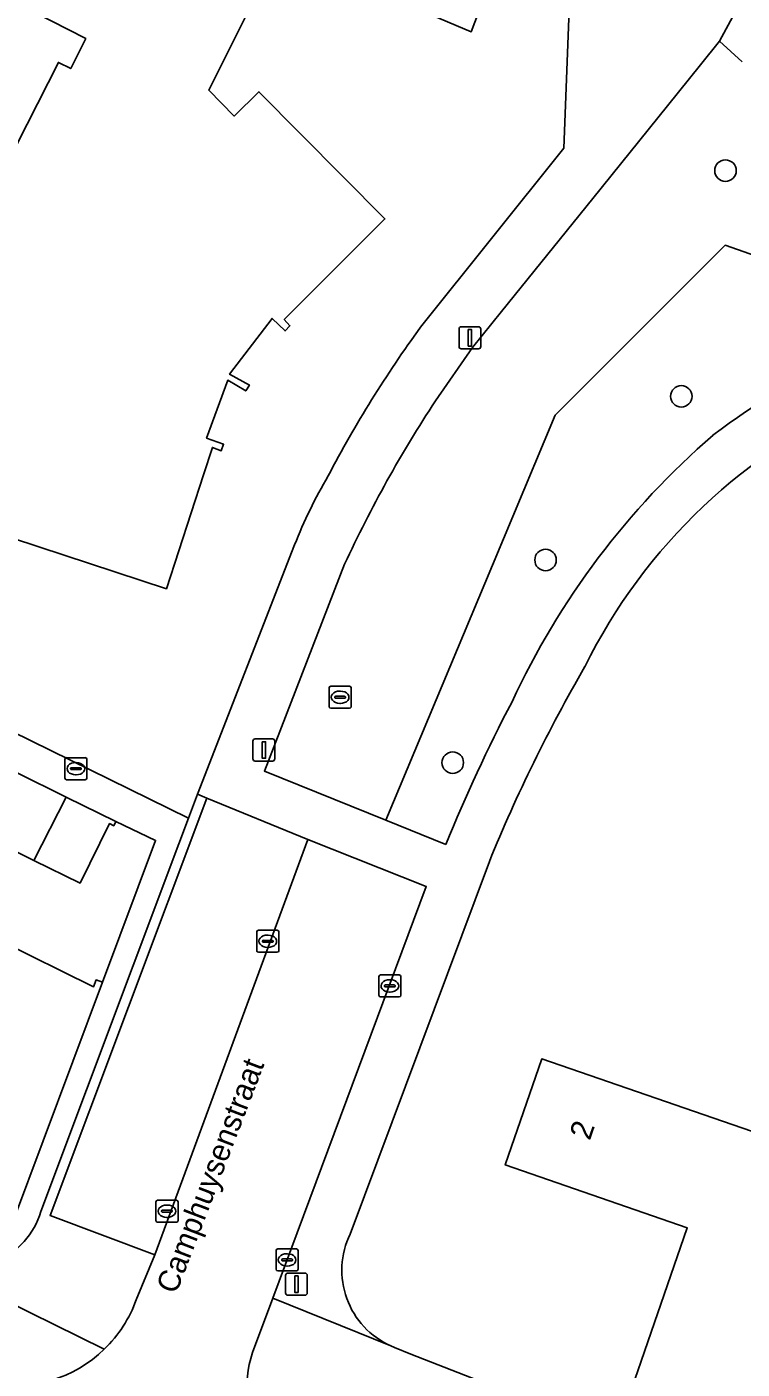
# Model space of a CAD drawing. Extents: x 160349 to 161355, y 381727 to 382854.
# Drawn here: x 160579.4 to 160611.9, y 381959.4 to 382020.3 of the extents above; entities that cross this region are included whole.
import ezdxf

# ---------------------------------------------------------------- set-up
doc = ezdxf.new("R2010")
doc.units = 0
for name, color, linetype in [('IMGEO_Boom', 7, 'Continuous'), ('IMGEO_Erf', 7, 'Continuous'), ('IMGEO_Groenvoorziening', 7, 'Continuous'), ('IMGEO_Kolk', 7, 'Continuous'), ('IMGEO_Lichtmast', 7, 'Continuous'), ('IMGEO_Muur', 7, 'Continuous'), ('IMGEO_Openbare_ruimte_label', 7, 'Continuous'), ('IMGEO_Pand', 7, 'Continuous'), ('IMGEO_Pand_nummerreeks', 7, 'Continuous'), ('IMGEO_Parkeervlak_open', 7, 'Continuous'), ('IMGEO_Rijbaan_lokaal_open', 7, 'Continuous'), ('IMGEO_Rioolput', 7, 'Continuous'), ('IMGEO_Voetpad_open', 7, 'Continuous')]:
    doc.layers.add(name, color=color, linetype=linetype)

msp = doc.modelspace()

# ---------------------------------------------------------------- linework, layer by layer
at = {"layer": 'IMGEO_Boom'}
for centre in [(160611.095, 382013.81), (160609.09, 382003.562), (160602.927, 381996.132), (160598.714, 381986.931)]:
    msp.add_circle(centre, 0.489, dxfattribs=at)
at = {"layer": 'IMGEO_Erf'}
for points in [[(160582.049, 382019.806), (160567.258, 382027.358), (160569.969, 382032.694), (160568.184, 382033.456), (160568.223, 382033.56), (160567.62, 382033.798), (160563.756, 382026.216), (160561.616, 382027.336), (160561.005, 382026.029), (160561.7, 382025.66), (160561.631, 382025.459), (160561.904, 382025.308), (160561.543, 382019.82), (160560.417, 381999.666), (160555.404, 381999.955), (160555.394, 381999.801), (160586.709, 381984.411), (160587.131, 381985.496), (160591.533, 381996.816)], [(160597.255, 382006.702), (160603.75, 382014.83), (160604.192, 382026.239)], [(160601.348, 382024.877), (160599.551, 382020.118), (160596.039, 382021.61)], [(160590.819, 382023.827), (160587.632, 382017.457), (160588.796, 382016.283), (160589.91, 382017.389), (160595.637, 382011.618), (160591.061, 382007.043), (160591.321, 382006.766), (160591.1, 382006.532), (160590.512, 382007.1), (160588.582, 382004.564), (160589.479, 382004.075), (160589.314, 382003.805), (160588.496, 382004.296), (160587.535, 382001.665), (160588.306, 382001.384), (160588.2, 382001.093), (160587.802, 382001.24), (160587.398, 382000), (160585.711, 381994.824), (160577.553, 381997.498)], [(160577.958, 382013.117), (160580.81, 382018.725), (160581.372, 382018.44), (160582.049, 382019.806)], [(160578.111, 381978.874), (160582.404, 381976.755), (160582.522, 381977.069), (160582.816, 381976.971), (160585.222, 381983.402), (160583.415, 381984.257), (160583.319, 381984.063), (160583.13, 381984.167), (160581.792, 381981.46), (160579.691, 381982.494), (160577.59, 381983.528)], [(160600.376, 381982.448), (160594.057, 381965.531)], [(160635.384, 381980.363), (160635.293, 381979.403), (160629.147, 381969.866), (160626.967, 381970.618), (160624.197, 381962.588), (160616.551, 381965.226), (160613.54, 381956.498), (160613.822, 381956.401), (160613.572, 381955.675), (160606.683, 381958.052), (160609.361, 381965.817), (160601.095, 381968.668), (160602.754, 381973.481), (160618.335, 381968.106), (160620.023, 381972.998), (160616.368, 381974.259), (160616.133, 381980.304), (160614.523, 381980.875)], [(160595.906, 381960.451), (160596.062, 381960.385), (160596.803, 381960.076), (160647.902, 381940.147)]]:
    msp.add_lwpolyline(points, dxfattribs=at)
for centre, radius, start, end in [((160640.632, 381975.066), 53.688, 143.89551, 152.38709), ((160627.701, 381979.922), 25.647, 113.12706, 153.69167), ((160612.091, 381988.744), 22.086, 149.51159, 158.56387), ((160667.438, 381955.049), 72.444, 149.98309, 157.77679), ((160597.437, 381963.885), 3.76, 154.03613, 245.96449)]:
    msp.add_arc(centre, radius, start, end, dxfattribs=at)
at = {"layer": 'IMGEO_Groenvoorziening'}
for points in [[(160611.853, 382018.745), (160610.821, 382019.688), (160609.956, 382018.614), (160608.46, 382016.757), (160605.07, 382012.549), (160600.93, 382007.409), (160599.614, 382005.776), (160597.93, 382003.354)], [(160593.801, 381995.937), (160590.164, 381986.55), (160595.677, 381984.32), (160600.512, 381995.895), (160603.366, 382002.7), (160611.086, 382010.42), (160614.745, 382009.139), (160618.989, 382008.371), (160622.943, 382011.327)], [(160623.793, 382007.511), (160622.943, 382011.327), (160618.989, 382008.371), (160614.745, 382009.139), (160611.086, 382010.42), (160603.366, 382002.7), (160600.512, 381995.895), (160595.677, 381984.32), (160598.403, 381983.217)]]:
    msp.add_lwpolyline(points, dxfattribs=at)
for centre, radius, start, end in [((160628.359, 381978.679), 29.191, 98.99987, 127.64836), ((160645.815, 381971.839), 57.325, 146.6494, 155.14174), ((160633.977, 381974.621), 35.889, 130.7934, 155.17039), ((160665.558, 381956.015), 72.455, 152.30312, 157.94924)]:
    msp.add_arc(centre, radius, start, end, dxfattribs=at)
at = {"layer": 'IMGEO_Kolk'}
for p, q in [((160581.105, 381986.231), (160581.105, 381987.083)), ((160581.18, 381987.157), (160582.032, 381987.157)), ((160581.593, 381986.937), (160581.618, 381986.937)), ((160582.106, 381987.083), (160582.106, 381986.231)), ((160581.364, 381986.651), (160581.364, 381986.663)), ((160581.802, 381986.614), (160581.404, 381986.614)), ((160581.407, 381986.7), (160581.805, 381986.7)), ((160581.616, 381986.377), (160581.591, 381986.377)), ((160581.848, 381986.663), (160581.848, 381986.651)), ((160582.032, 381986.157), (160581.18, 381986.157)), ((160589.816, 381978.395), (160589.816, 381979.247)), ((160589.891, 381979.321), (160590.743, 381979.321)), ((160590.304, 381979.101), (160590.329, 381979.101)), ((160590.817, 381979.247), (160590.817, 381978.395)), ((160590.075, 381978.815), (160590.075, 381978.827)), ((160590.513, 381978.778), (160590.115, 381978.778)), ((160590.118, 381978.864), (160590.516, 381978.864)), ((160590.327, 381978.541), (160590.302, 381978.541)), ((160590.559, 381978.827), (160590.559, 381978.815)), ((160590.743, 381978.321), (160589.891, 381978.321)), ((160595.358, 381976.368), (160595.358, 381977.22)), ((160595.433, 381977.294), (160596.285, 381977.294)), ((160596.359, 381977.22), (160596.359, 381976.368)), ((160595.617, 381976.788), (160595.617, 381976.8)), ((160596.055, 381976.751), (160595.657, 381976.751)), ((160595.66, 381976.837), (160596.058, 381976.837)), ((160595.869, 381976.514), (160595.844, 381976.514)), ((160595.846, 381977.074), (160595.871, 381977.074)), ((160596.101, 381976.8), (160596.101, 381976.788)), ((160596.285, 381976.294), (160595.433, 381976.294)), ((160585.239, 381966.14), (160585.239, 381966.992)), ((160585.314, 381967.066), (160586.166, 381967.066)), ((160585.727, 381966.846), (160585.752, 381966.846)), ((160586.24, 381966.992), (160586.24, 381966.14)), ((160585.498, 381966.56), (160585.498, 381966.572)), ((160585.936, 381966.523), (160585.538, 381966.523)), ((160585.541, 381966.609), (160585.939, 381966.609)), ((160585.75, 381966.286), (160585.725, 381966.286)), ((160585.982, 381966.572), (160585.982, 381966.56)), ((160586.166, 381966.066), (160585.314, 381966.066)), ((160590.692, 381963.928), (160590.692, 381964.78)), ((160590.767, 381964.854), (160591.619, 381964.854)), ((160590.951, 381964.348), (160590.951, 381964.36)), ((160590.994, 381964.397), (160591.392, 381964.397)), ((160591.18, 381964.634), (160591.205, 381964.634)), ((160591.435, 381964.36), (160591.435, 381964.348)), ((160591.693, 381964.78), (160591.693, 381963.928)), ((160591.619, 381963.854), (160590.767, 381963.854)), ((160591.389, 381964.311), (160590.991, 381964.311)), ((160591.203, 381964.074), (160591.178, 381964.074))]:
    msp.add_line(p, q, dxfattribs=at)
for points in [[(160581.105, 381986.231), (160581.105, 381987.083)], [(160581.18, 381987.157), (160582.032, 381987.157)], [(160582.106, 381987.083), (160582.106, 381986.231)], [(160582.032, 381986.157), (160581.18, 381986.157)], [(160589.816, 381978.395), (160589.816, 381979.247)], [(160589.891, 381979.321), (160590.743, 381979.321)], [(160590.817, 381979.247), (160590.817, 381978.395)], [(160590.743, 381978.321), (160589.891, 381978.321)], [(160595.358, 381976.368), (160595.358, 381977.22)], [(160595.433, 381977.294), (160596.285, 381977.294)], [(160596.359, 381977.22), (160596.359, 381976.368)], [(160596.285, 381976.294), (160595.433, 381976.294)], [(160585.239, 381966.14), (160585.239, 381966.992)], [(160585.314, 381967.066), (160586.166, 381967.066)], [(160586.24, 381966.992), (160586.24, 381966.14)], [(160586.166, 381966.066), (160585.314, 381966.066)], [(160590.692, 381963.928), (160590.692, 381964.78)], [(160590.767, 381964.854), (160591.619, 381964.854)], [(160591.693, 381964.78), (160591.693, 381963.928)], [(160591.619, 381963.854), (160590.767, 381963.854)]]:
    msp.add_lwpolyline(points, dxfattribs=at)
for centre, radius, start, end in [((160581.182, 381987.081), 0.0765, 91.55205, 178.44795), ((160581.182, 381987.081), 0.0765, 91.55205, 178.44795), ((160582.03, 381987.081), 0.0765, 1.55205, 88.44795), ((160582.03, 381987.081), 0.0765, 1.55205, 88.44795), ((160581.404, 381986.66), 0.0403, 85.87752, 175.75265), ((160581.401, 381986.65), 0.0366, 178.93798, 274.71019), ((160581.805, 381986.657), 0.043, 264.86636, 352.45326), ((160581.809, 381986.662), 0.0386, 1.73085, 96.63898), ((160581.182, 381986.233), 0.0765, 181.55205, 268.44795), ((160581.182, 381986.233), 0.0765, 181.55205, 268.44795), ((160582.03, 381986.233), 0.0765, 271.55205, 358.44795), ((160582.03, 381986.233), 0.0765, 271.55205, 358.44795), ((160589.893, 381979.245), 0.0765, 91.55205, 178.44795), ((160589.893, 381979.245), 0.0765, 91.55205, 178.44795), ((160590.741, 381979.245), 0.0765, 1.55205, 88.44795), ((160590.741, 381979.245), 0.0765, 1.55205, 88.44795), ((160589.893, 381978.397), 0.0765, 181.55205, 268.44795), ((160589.893, 381978.397), 0.0765, 181.55205, 268.44795), ((160590.115, 381978.824), 0.0403, 85.87752, 175.75265), ((160590.112, 381978.814), 0.0366, 178.93798, 274.71019), ((160590.516, 381978.821), 0.043, 264.86636, 352.45326), ((160590.52, 381978.826), 0.0386, 1.73085, 96.63898), ((160590.741, 381978.397), 0.0765, 271.55205, 358.44795), ((160590.741, 381978.397), 0.0765, 271.55205, 358.44795), ((160595.435, 381977.218), 0.0765, 91.55205, 178.44795), ((160595.435, 381977.218), 0.0765, 91.55205, 178.44795), ((160596.283, 381977.218), 0.0765, 1.55205, 88.44795), ((160596.283, 381977.218), 0.0765, 1.55205, 88.44795), ((160595.657, 381976.797), 0.0403, 85.87752, 175.75265), ((160595.654, 381976.787), 0.0366, 178.93798, 274.71019), ((160596.058, 381976.794), 0.043, 264.86636, 352.45326), ((160596.062, 381976.799), 0.0386, 1.73085, 96.63898), ((160595.435, 381976.37), 0.0765, 181.55205, 268.44795), ((160595.435, 381976.37), 0.0765, 181.55205, 268.44795), ((160596.283, 381976.37), 0.0765, 271.55205, 358.44795), ((160596.283, 381976.37), 0.0765, 271.55205, 358.44795), ((160585.316, 381966.99), 0.0765, 91.55205, 178.44795), ((160585.316, 381966.99), 0.0765, 91.55205, 178.44795), ((160586.164, 381966.99), 0.0765, 1.55205, 88.44795), ((160586.164, 381966.99), 0.0765, 1.55205, 88.44795), ((160585.538, 381966.569), 0.0403, 85.87752, 175.75265), ((160585.535, 381966.559), 0.0366, 178.93798, 274.71019), ((160585.939, 381966.566), 0.043, 264.86636, 352.45326), ((160585.943, 381966.571), 0.0386, 1.73085, 96.63898), ((160585.316, 381966.142), 0.0765, 181.55205, 268.44795), ((160585.316, 381966.142), 0.0765, 181.55205, 268.44795), ((160586.164, 381966.142), 0.0765, 271.55205, 358.44795), ((160586.164, 381966.142), 0.0765, 271.55205, 358.44795), ((160590.769, 381964.778), 0.0765, 91.55205, 178.44795), ((160590.769, 381964.778), 0.0765, 91.55205, 178.44795), ((160590.991, 381964.357), 0.0403, 85.87752, 175.75265), ((160590.988, 381964.347), 0.0366, 178.93798, 274.71019), ((160591.392, 381964.354), 0.043, 264.86636, 352.45326), ((160591.396, 381964.359), 0.0386, 1.73085, 96.63898), ((160591.617, 381964.778), 0.0765, 1.55205, 88.44795), ((160591.617, 381964.778), 0.0765, 1.55205, 88.44795), ((160590.769, 381963.93), 0.0765, 181.55205, 268.44795), ((160590.769, 381963.93), 0.0765, 181.55205, 268.44795), ((160591.617, 381963.93), 0.0765, 271.55205, 358.44795), ((160591.617, 381963.93), 0.0765, 271.55205, 358.44795)]:
    msp.add_arc(centre, radius, start, end, dxfattribs=at)
for centre, major_axis, ratio, start_param, end_param in [((160581.592, 381986.657), (-0.387, 0.002), 0.722429, 4.712389, 7.853982), ((160581.617, 381986.657), (-0.39, 0.002), 0.717154, 1.570796, 4.712389), ((160590.303, 381978.821), (-0.387, 0.002), 0.722429, 4.712389, 7.853982), ((160590.328, 381978.821), (-0.39, 0.002), 0.717154, 1.570796, 4.712389), ((160595.845, 381976.794), (-0.387, 0.002), 0.722429, 4.712389, 7.853982), ((160595.87, 381976.794), (-0.39, 0.002), 0.717154, 1.570796, 4.712389), ((160585.726, 381966.566), (-0.387, 0.002), 0.722429, 4.712389, 7.853982), ((160585.751, 381966.566), (-0.39, 0.002), 0.717154, 1.570796, 4.712389), ((160591.179, 381964.354), (-0.387, 0.002), 0.722429, 4.712389, 7.853982), ((160591.204, 381964.354), (-0.39, 0.002), 0.717154, 1.570796, 4.712389)]:
    msp.add_ellipse(centre, major_axis=major_axis, ratio=ratio, start_param=start_param, end_param=end_param, dxfattribs=at)
at = {"layer": 'IMGEO_Lichtmast'}
for p, q in [((160598.998, 382005.819), (160598.998, 382006.619)), ((160598.998, 382006.619), (160598.998, 382005.819)), ((160599.098, 382006.719), (160599.888, 382006.719)), ((160599.888, 382006.719), (160599.098, 382006.719)), ((160599.988, 382006.619), (160599.988, 382005.819)), ((160599.988, 382005.819), (160599.988, 382006.619)), ((160599.888, 382005.719), (160599.098, 382005.719)), ((160599.098, 382005.719), (160599.888, 382005.719)), ((160589.644, 381987.106), (160589.644, 381987.906)), ((160589.644, 381987.906), (160589.644, 381987.106)), ((160589.744, 381988.006), (160590.534, 381988.006)), ((160590.534, 381988.006), (160589.744, 381988.006)), ((160590.634, 381987.906), (160590.634, 381987.106)), ((160590.634, 381987.106), (160590.634, 381987.906)), ((160590.534, 381987.006), (160589.744, 381987.006)), ((160589.744, 381987.006), (160590.534, 381987.006)), ((160591.22, 381963.754), (160592.01, 381963.754)), ((160592.01, 381963.754), (160591.22, 381963.754)), ((160591.12, 381962.854), (160591.12, 381963.654)), ((160591.12, 381963.654), (160591.12, 381962.854)), ((160592.11, 381963.654), (160592.11, 381962.854)), ((160592.11, 381962.854), (160592.11, 381963.654)), ((160592.01, 381962.754), (160591.22, 381962.754)), ((160591.22, 381962.754), (160592.01, 381962.754))]:
    msp.add_line(p, q, dxfattribs=at)
for points in [[(160599.418, 382006.594), (160599.568, 382006.594), (160599.568, 382005.844), (160599.418, 382005.844), (160599.418, 382006.594)], [(160590.064, 381987.881), (160590.214, 381987.881), (160590.214, 381987.131), (160590.064, 381987.131), (160590.064, 381987.881)], [(160591.54, 381963.629), (160591.69, 381963.629), (160591.69, 381962.879), (160591.54, 381962.879), (160591.54, 381963.629)]]:
    msp.add_lwpolyline(points, dxfattribs=at)
for centre, start, end in [((160599.098, 382006.619), 90, 180), ((160599.098, 382006.619), 90, 180), ((160599.888, 382006.619), 0, 90), ((160599.888, 382006.619), 360, 90), ((160599.098, 382005.819), 180, 270), ((160599.098, 382005.819), 180, 270), ((160599.888, 382005.819), 270, 0), ((160599.888, 382005.819), 270, 0), ((160589.744, 381987.906), 90, 180), ((160589.744, 381987.906), 90, 180), ((160590.534, 381987.906), 0, 90), ((160590.534, 381987.906), 360, 90), ((160589.744, 381987.106), 180, 270), ((160589.744, 381987.106), 180, 270), ((160590.534, 381987.106), 270, 0), ((160590.534, 381987.106), 270, 0), ((160591.22, 381963.654), 90, 180), ((160591.22, 381963.654), 90, 180), ((160592.01, 381963.654), 0, 90), ((160592.01, 381963.654), 360, 90), ((160591.22, 381962.854), 180, 270), ((160591.22, 381962.854), 180, 270), ((160592.01, 381962.854), 270, 0), ((160592.01, 381962.854), 270, 0)]:
    msp.add_arc(centre, 0.1, start, end, dxfattribs=at)
at = {"layer": 'IMGEO_Muur'}
for points in [[(160583.415, 381984.257), (160585.222, 381983.402)], [(160585.222, 381983.402), (160582.816, 381976.971)]]:
    msp.add_lwpolyline(points, dxfattribs=at)
at = {"layer": 'IMGEO_Pand'}
for points in [[(160567.258, 382027.358), (160582.049, 382019.806), (160581.372, 382018.44), (160580.81, 382018.725), (160577.958, 382013.117)], [(160596.039, 382021.61), (160599.551, 382020.118), (160601.348, 382024.877)], [(160577.553, 381997.498), (160585.711, 381994.824), (160587.398, 382000), (160587.802, 382001.24), (160588.2, 382001.093), (160588.306, 382001.384), (160587.535, 382001.665), (160588.496, 382004.296), (160589.314, 382003.805), (160589.479, 382004.075), (160588.582, 382004.564), (160590.512, 382007.1), (160591.1, 382006.532), (160591.321, 382006.766), (160591.061, 382007.043), (160595.637, 382011.618), (160589.91, 382017.389), (160588.796, 382016.283), (160587.632, 382017.457), (160590.819, 382023.827)], [(160614.523, 381980.875), (160616.133, 381980.304), (160616.368, 381974.259), (160620.023, 381972.998), (160618.335, 381968.106), (160602.754, 381973.481), (160601.095, 381968.668), (160609.361, 381965.817), (160606.683, 381958.052), (160613.572, 381955.675), (160613.822, 381956.401), (160613.54, 381956.498), (160616.551, 381965.226), (160624.197, 381962.588), (160626.967, 381970.618), (160629.147, 381969.866), (160635.293, 381979.403), (160635.384, 381980.363), (160635.73, 381990.411), (160635.411, 381990.698), (160628.984, 381993.238), (160623.552, 381995.112), (160619.629, 381990.623), (160617.992, 381991.183)]]:
    msp.add_lwpolyline(points, dxfattribs=at)
for points in [[(160581.163, 381985.37), (160578.911, 381986.482), (160578.816, 381986.29), (160578.928, 381986.235), (160577.59, 381983.528), (160579.691, 381982.494)], [(160581.163, 381985.37), (160579.691, 381982.494), (160581.792, 381981.46), (160583.13, 381984.167), (160583.319, 381984.063), (160583.415, 381984.257)], [(160578.114, 381979.253), (160572.398, 381967.657), (160572.541, 381967.588), (160572.963, 381968.444), (160577.311, 381966.279), (160576.92, 381965.424), (160577.207, 381965.293), (160577.95, 381966.809), (160578.557, 381966.501), (160578.479, 381966.261), (160578.778, 381966.154), (160582.816, 381976.971), (160582.522, 381977.069), (160582.404, 381976.755), (160578.111, 381978.874), (160578.254, 381979.185)]]:
    msp.add_lwpolyline(points, close=True, dxfattribs=at)
at = {"layer": 'IMGEO_Parkeervlak_open'}
msp.add_lwpolyline([(160592.127, 381983.448), (160587.552, 381985.316), (160580.429, 381966.378), (160585.182, 381964.593)], close=True, dxfattribs=at)
at = {"layer": 'IMGEO_Rijbaan_lokaal_open'}
for points in [[(160597.508, 381981.306), (160592.127, 381983.448), (160585.182, 381964.593), (160584.346, 381962.544)], [(160589.617, 381960.145), (160590.54, 381962.62), (160597.508, 381981.306)]]:
    msp.add_lwpolyline(points, dxfattribs=at)
for centre, radius, start, end in [((160578.739, 381964.588), 5.968, 314.12442, 339.97181), ((160578.756, 381964.577), 5.948, 259.76782, 314.08545), ((160595.052, 381958.427), 5.7, 162.45521, 248.06829)]:
    msp.add_arc(centre, radius, start, end, dxfattribs=at)
at = {"layer": 'IMGEO_Rioolput'}
for p, q in [((160593.1, 381989.473), (160593.1, 381990.325)), ((160593.175, 381990.399), (160594.027, 381990.399)), ((160593.402, 381989.942), (160593.8, 381989.942)), ((160593.588, 381990.179), (160593.613, 381990.179)), ((160594.101, 381990.325), (160594.101, 381989.473)), ((160594.027, 381989.399), (160593.175, 381989.399)), ((160593.359, 381989.893), (160593.359, 381989.905)), ((160593.797, 381989.856), (160593.399, 381989.856)), ((160593.611, 381989.619), (160593.586, 381989.619)), ((160593.843, 381989.905), (160593.843, 381989.893))]:
    msp.add_line(p, q, dxfattribs=at)
for points in [[(160593.1, 381989.473), (160593.1, 381990.325)], [(160593.175, 381990.399), (160594.027, 381990.399)], [(160594.101, 381990.325), (160594.101, 381989.473)], [(160594.027, 381989.399), (160593.175, 381989.399)]]:
    msp.add_lwpolyline(points, dxfattribs=at)
for centre, radius, start, end in [((160593.177, 381990.323), 0.0765, 91.55205, 178.44795), ((160593.177, 381990.323), 0.0765, 91.55205, 178.44795), ((160593.399, 381989.902), 0.0403, 85.87752, 175.75265), ((160593.804, 381989.904), 0.0386, 1.73085, 96.63898), ((160594.025, 381990.323), 0.0765, 1.55205, 88.44795), ((160594.025, 381990.323), 0.0765, 1.55205, 88.44795), ((160593.177, 381989.475), 0.0765, 181.55205, 268.44795), ((160593.177, 381989.475), 0.0765, 181.55205, 268.44795), ((160593.396, 381989.892), 0.0366, 178.93798, 274.71019), ((160593.8, 381989.899), 0.043, 264.86636, 352.45326), ((160594.025, 381989.475), 0.0765, 271.55205, 358.44795), ((160594.025, 381989.475), 0.0765, 271.55205, 358.44795)]:
    msp.add_arc(centre, radius, start, end, dxfattribs=at)
for centre, major_axis, ratio, start_param, end_param in [((160593.587, 381989.899), (-0.387, 0.002), 0.722429, 4.712389, 7.853982), ((160593.612, 381989.899), (-0.39, 0.002), 0.717154, 1.570796, 4.712389)]:
    msp.add_ellipse(centre, major_axis=major_axis, ratio=ratio, start_param=start_param, end_param=end_param, dxfattribs=at)
at = {"layer": 'IMGEO_Voetpad_open'}
for points in [[(160612.329, 382027.732), (160612.492, 382028.495), (160611.134, 382028.835), (160610.04, 382029.166), (160605.827, 382030.426), (160605.266, 382028.988), (160604.192, 382026.239), (160603.75, 382014.83), (160597.255, 382006.702)], [(160612.714, 382023.192), (160610.821, 382019.688), (160611.853, 382018.745)], [(160610.821, 382019.688), (160612.714, 382023.192), (160611.839, 382023.072)], [(160597.93, 382003.354), (160599.614, 382005.776), (160600.93, 382007.409), (160605.07, 382012.549), (160608.46, 382016.757), (160609.956, 382018.614), (160610.821, 382019.688)], [(160580.011, 381966.548), (160586.279, 381983.246), (160586.709, 381984.411), (160555.394, 381999.801)], [(160591.533, 381996.816), (160587.131, 381985.496), (160587.552, 381985.316), (160592.127, 381983.448), (160597.508, 381981.306), (160590.54, 381962.62), (160595.906, 381960.451)], [(160598.403, 381983.217), (160595.677, 381984.32), (160590.164, 381986.55), (160593.801, 381995.937)], [(160578.911, 381986.482), (160581.163, 381985.37), (160583.415, 381984.257), (160585.222, 381983.402), (160582.816, 381976.971), (160578.778, 381966.154)], [(160585.182, 381964.593), (160580.429, 381966.378), (160587.552, 381985.316), (160587.131, 381985.496), (160586.709, 381984.411), (160586.279, 381983.246), (160580.011, 381966.548)], [(160594.057, 381965.531), (160600.376, 381982.448)], [(160584.346, 381962.544), (160585.182, 381964.593)], [(160582.894, 381960.304), (160574.983, 381964.188)], [(160574.983, 381964.188), (160582.894, 381960.304)], [(160658.252, 381931.82), (160659.186, 381934.173), (160647.902, 381940.147), (160596.803, 381960.076), (160596.062, 381960.385), (160595.906, 381960.451), (160590.54, 381962.62), (160589.617, 381960.145)]]:
    msp.add_lwpolyline(points, dxfattribs=at)
for centre, radius, start, end in [((160628.359, 381978.679), 29.191, 98.99987, 127.64836), ((160640.632, 381975.066), 53.688, 143.89551, 152.38709), ((160645.815, 381971.839), 57.325, 146.6494, 155.14174), ((160627.701, 381979.922), 25.647, 113.12706, 153.69167), ((160633.977, 381974.621), 35.889, 130.7934, 155.17039), ((160612.091, 381988.744), 22.086, 149.51159, 158.56387), ((160667.438, 381955.049), 72.444, 149.98309, 157.77679), ((160665.558, 381956.015), 72.455, 152.30312, 157.94924), ((160576.423, 381967.656), 3.755, 247.45259, 342.83546), ((160576.423, 381967.656), 3.755, 247.45259, 342.83546), ((160597.437, 381963.885), 3.76, 154.03613, 245.96449), ((160578.739, 381964.588), 5.968, 314.12442, 339.97181), ((160578.756, 381964.577), 5.948, 259.76782, 314.08545), ((160595.052, 381958.427), 5.7, 162.45521, 248.06829)]:
    msp.add_arc(centre, radius, start, end, dxfattribs=at)

# ---------------------------------------------------------------- texts
at = {"layer": 'IMGEO_Openbare_ruimte_label'}
msp.add_text('Camphuysenstraat', height=1, rotation=69.02829, dxfattribs=at).set_placement((160586.152, 381962.763))
at = {"layer": 'IMGEO_Pand_nummerreeks'}
msp.add_text('2', height=1, rotation=70.98136, dxfattribs=at).set_placement((160604.935, 381969.743))

doc.saveas('drawing.dxf')
